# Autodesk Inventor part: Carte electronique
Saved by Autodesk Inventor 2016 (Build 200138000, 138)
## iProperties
Created: 2013-08
Part Number: Carte electronique
Material: Générique
Document SubType Name: Modeling
Designer: hilarion
Density: 1 g/cm^3
Appearance: Par défaut
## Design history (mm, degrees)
node "Carte electronique1"
node "Carte electronique"
node "Base1"
